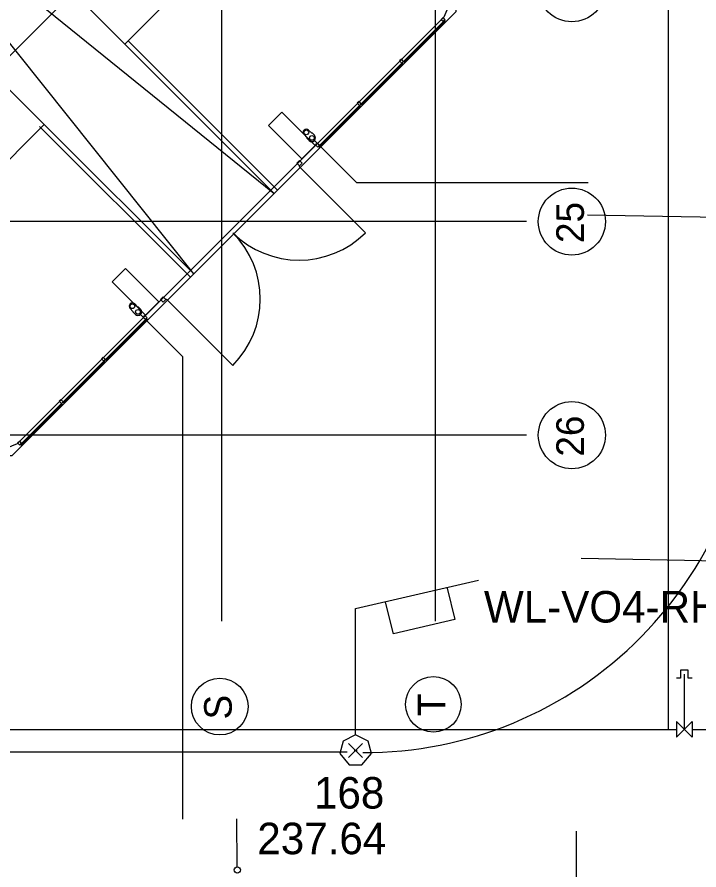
# Model space of a CAD drawing. Extents: x -264222 to -263592, y -1242345 to -1242048.
# Drawn here: x -263808.81 to -263787.18, y -1242254.6 to -1242227.54 of the extents above; entities that cross this region are included whole.
import ezdxf

# ---------------------------------------------------------------- set-up
doc = ezdxf.new("R2010")
doc.units = 0
for name, color, linetype in [('BOD_CISLO', 7, 'Continuous'), ('BOD_SYMBOL', 7, 'Continuous'), ('BOD_VYSKA', 7, 'Continuous'), ('HESCON_OSI_STAVBY_KFA', 7, 'Continuous'), ('KFA_2D_SITUACIA_DSP', 7, 'Continuous'), ('KFA_SO_62-1_VO_LAMPY_MERANE', 7, 'Continuous'), ('KFA_SO_62-1_VO_POPIS_LAMP_PROJEKT', 7, 'Continuous'), ('KFA_SO_62-1_VO_TRASA_KABLOV_PROJEKT', 7, 'Continuous')]:
    doc.layers.add(name, color=color, linetype=linetype)

msp = doc.modelspace()

# ---------------------------------------------------------------- linework, layer by layer
at = {"layer": 'BOD_SYMBOL'}
for p, q in [((-263798.289, -1242251.029), (-263797.847, -1242250.587)), ((-263797.847, -1242251.029), (-263798.289, -1242250.587))]:
    msp.add_line(p, q, dxfattribs=at)
at = {"layer": 'HESCON_OSI_STAVBY_KFA'}
for p, q in [((-263802.318, -1242083.237), (-263802.318, -1242246.707)), ((-263795.543, -1242083.237), (-263795.543, -1242246.707)), ((-263792.653, -1242234.032), (-263911.523, -1242234.032)), ((-263792.653, -1242234.032), (-263792.653, -1242234.032)), ((-263792.653, -1242240.807), (-263911.523, -1242240.807)), ((-263792.653, -1242240.807), (-263792.653, -1242240.807))]:
    msp.add_line(p, q, dxfattribs=at)
for centre, radius in [((-263791.21, -1242226.632), 1.064), ((-263791.21, -1242234.032), 1.064), ((-263791.21, -1242240.807), 1.064), ((-263802.378, -1242249.416), 0.899), ((-263795.603, -1242249.345), 0.882)]:
    msp.add_circle(centre, radius, dxfattribs=at)
at = {"layer": 'KFA_2D_SITUACIA_DSP'}
for p, q in [((-263788.143, -1242250.14), (-263788.143, -1242082.64)), ((-263795.043, -1242226.995), (-263795.272, -1242227.55)), ((-263795.272, -1242227.55), (-263808.8, -1242241.078)), ((-263796.558, -1242228.963), (-263795.25, -1242227.654)), ((-263795.232, -1242227.672), (-263796.541, -1242228.98)), ((-263795.297, -1242227.56), (-263795.354, -1242227.617)), ((-263795.354, -1242227.617), (-263795.283, -1242227.688)), ((-263795.227, -1242227.631), (-263795.297, -1242227.56)), ((-263795.283, -1242227.688), (-263795.255, -1242227.659)), ((-263795.255, -1242227.659), (-263795.227, -1242227.631)), ((-263795.25, -1242227.654), (-263795.232, -1242227.672)), ((-263805.283, -1242228.297), (-263800.546, -1242233.035)), ((-263805.389, -1242228.403), (-263800.652, -1242233.141)), ((-263796.59, -1242228.994), (-263797.898, -1242230.303)), ((-263797.881, -1242230.32), (-263796.572, -1242229.012)), ((-263796.617, -1242228.879), (-263796.673, -1242228.936)), ((-263796.673, -1242228.936), (-263796.602, -1242229.007)), ((-263796.546, -1242228.95), (-263796.617, -1242228.879)), ((-263796.602, -1242229.007), (-263796.574, -1242228.978)), ((-263796.572, -1242229.012), (-263796.59, -1242228.994)), ((-263796.574, -1242228.978), (-263796.546, -1242228.95)), ((-263796.541, -1242228.98), (-263796.558, -1242228.963)), ((-263797.961, -1242230.223), (-263798.017, -1242230.28)), ((-263797.89, -1242230.294), (-263797.961, -1242230.223)), ((-263797.934, -1242230.338), (-263799.242, -1242231.647)), ((-263799.225, -1242231.664), (-263797.916, -1242230.356)), ((-263798.017, -1242230.28), (-263797.946, -1242230.351)), ((-263797.946, -1242230.351), (-263797.918, -1242230.322)), ((-263797.916, -1242230.356), (-263797.934, -1242230.338)), ((-263797.918, -1242230.322), (-263797.89, -1242230.294)), ((-263797.898, -1242230.303), (-263797.881, -1242230.32)), ((-263800.834, -1242230.985), (-263800.41, -1242230.561)), ((-263800.41, -1242230.561), (-263799.349, -1242231.622)), ((-263808.093, -1242231.016), (-263803.31, -1242235.799)), ((-263807.987, -1242230.91), (-263803.204, -1242235.693)), ((-263799.774, -1242232.046), (-263800.834, -1242230.985)), ((-263799.705, -1242231.275), (-263799.617, -1242231.364)), ((-263799.559, -1242231.13), (-263799.471, -1242231.218)), ((-263799.471, -1242231.218), (-263799.451, -1242231.218)), ((-263799.373, -1242231.296), (-263799.451, -1242231.218)), ((-263799.451, -1242231.218), (-263799.373, -1242231.296)), ((-263799.617, -1242231.364), (-263799.617, -1242231.383)), ((-263799.617, -1242231.383), (-263799.538, -1242231.462)), ((-263799.402, -1242231.432), (-263798.041, -1242232.793)), ((-263799.28, -1242231.543), (-263799.336, -1242231.599)), ((-263799.209, -1242231.613), (-263799.28, -1242231.543)), ((-263799.349, -1242231.622), (-263799.774, -1242232.046)), ((-263799.336, -1242231.599), (-263799.266, -1242231.67)), ((-263799.266, -1242231.67), (-263799.237, -1242231.642)), ((-263799.242, -1242231.647), (-263799.225, -1242231.664)), ((-263799.237, -1242231.642), (-263799.209, -1242231.613)), ((-263799.929, -1242232.178), (-263799.844, -1242232.093)), ((-263799.844, -1242232.093), (-263799.759, -1242232.178)), ((-263799.844, -1242232.263), (-263799.929, -1242232.178)), ((-263799.844, -1242232.263), (-263799.862, -1242232.281)), ((-263799.862, -1242232.281), (-263797.758, -1242234.384)), ((-263799.759, -1242232.178), (-263799.844, -1242232.263)), ((-263798.041, -1242232.793), (-263790.695, -1242232.793)), ((-263781.818, -1242233.99), (-263790.714, -1242233.827)), ((-263805.365, -1242235.516), (-263805.789, -1242235.94)), ((-263804.304, -1242236.576), (-263805.365, -1242235.516)), ((-263805.789, -1242235.94), (-263804.728, -1242237.001)), ((-263804.172, -1242236.421), (-263804.257, -1242236.506)), ((-263804.087, -1242236.506), (-263804.172, -1242236.421)), ((-263805.075, -1242236.645), (-263804.986, -1242236.733)), ((-263804.728, -1242237.001), (-263804.304, -1242236.576)), ((-263804.257, -1242236.506), (-263804.172, -1242236.591)), ((-263804.172, -1242236.591), (-263804.087, -1242236.506)), ((-263804.087, -1242236.506), (-263804.069, -1242236.488)), ((-263804.069, -1242236.488), (-263801.966, -1242238.592)), ((-263805.22, -1242236.791), (-263805.132, -1242236.879)), ((-263805.132, -1242236.879), (-263805.132, -1242236.899)), ((-263805.132, -1242236.899), (-263805.054, -1242236.977)), ((-263804.986, -1242236.733), (-263804.967, -1242236.733)), ((-263804.888, -1242236.812), (-263804.967, -1242236.733)), ((-263804.967, -1242236.733), (-263804.888, -1242236.812)), ((-263804.918, -1242236.948), (-263803.556, -1242238.308)), ((-263806.012, -1242238.416), (-263804.703, -1242237.108)), ((-263804.686, -1242237.125), (-263805.994, -1242238.434)), ((-263804.807, -1242237.07), (-263804.751, -1242237.014)), ((-263804.737, -1242237.141), (-263804.807, -1242237.07)), ((-263804.751, -1242237.014), (-263804.68, -1242237.084)), ((-263804.708, -1242237.113), (-263804.737, -1242237.141)), ((-263804.68, -1242237.084), (-263804.708, -1242237.113)), ((-263804.703, -1242237.108), (-263804.686, -1242237.125)), ((-263806.127, -1242238.389), (-263806.07, -1242238.333)), ((-263806.07, -1242238.333), (-263805.999, -1242238.404)), ((-263803.556, -1242238.308), (-263803.556, -1242252.989)), ((-263807.356, -1242239.76), (-263806.047, -1242238.452)), ((-263806.03, -1242238.469), (-263807.338, -1242239.778)), ((-263806.056, -1242238.46), (-263806.127, -1242238.389)), ((-263806.028, -1242238.432), (-263806.056, -1242238.46)), ((-263806.047, -1242238.452), (-263806.03, -1242238.469)), ((-263805.999, -1242238.404), (-263806.028, -1242238.432)), ((-263805.994, -1242238.434), (-263806.012, -1242238.416)), ((-263807.471, -1242239.733), (-263807.414, -1242239.677)), ((-263807.414, -1242239.677), (-263807.343, -1242239.748)), ((-263807.387, -1242239.792), (-263808.696, -1242241.1)), ((-263808.678, -1242241.118), (-263807.37, -1242239.809)), ((-263807.4, -1242239.804), (-263807.471, -1242239.733)), ((-263807.372, -1242239.776), (-263807.4, -1242239.804)), ((-263807.37, -1242239.809), (-263807.387, -1242239.792)), ((-263807.343, -1242239.748), (-263807.372, -1242239.776)), ((-263807.338, -1242239.778), (-263807.356, -1242239.76)), ((-263808.79, -1242241.053), (-263808.733, -1242240.996)), ((-263808.733, -1242240.996), (-263808.662, -1242241.067)), ((-263808.8, -1242241.078), (-263809.355, -1242241.307)), ((-263808.719, -1242241.123), (-263808.79, -1242241.053)), ((-263808.691, -1242241.095), (-263808.719, -1242241.123)), ((-263808.696, -1242241.1), (-263808.678, -1242241.118)), ((-263808.662, -1242241.067), (-263808.691, -1242241.095)), ((-263781.818, -1242244.885), (-263790.914, -1242244.718)), ((-263787.768, -1242248.265), (-263787.768, -1242248.515)), ((-263787.518, -1242248.265), (-263787.768, -1242248.265)), ((-263787.518, -1242248.515), (-263787.518, -1242248.265)), ((-263787.768, -1242248.515), (-263787.893, -1242248.515)), ((-263787.643, -1242250.14), (-263787.643, -1242248.39)), ((-263787.393, -1242248.515), (-263787.518, -1242248.515)), ((-263787.893, -1242250.39), (-263787.393, -1242249.89)), ((-263787.893, -1242249.89), (-263787.893, -1242250.39)), ((-263787.393, -1242250.39), (-263787.893, -1242249.89)), ((-263787.393, -1242249.89), (-263787.393, -1242250.39)), ((-263924.143, -1242250.14), (-263788.143, -1242250.14)), ((-263788.143, -1242250.14), (-263787.893, -1242250.14)), ((-263788.143, -1242250.14), (-263787.893, -1242250.14)), ((-263787.393, -1242250.14), (-263786.693, -1242250.14)), ((-263801.822, -1242254.497), (-263801.837, -1242252.972)), ((-263791.063, -1242265.427), (-263791.063, -1242253.362))]:
    msp.add_line(p, q, dxfattribs=at)
for points in [[(-263794.893, -1242227.382), (-263808.968, -1242241.457), (-263894.968, -1242241.457), (-263909.043, -1242227.382), (-263909.043, -1242196.333), (-263914.143, -1242196.333), (-263914.143, -1242132.433), (-263909.043, -1242132.433), (-263909.043, -1242101.382), (-263894.968, -1242087.307), (-263808.968, -1242087.307), (-263794.893, -1242101.382), (-263794.893, -1242227.382)], [(-263909.043, -1242125.432), (-263902.343, -1242125.432), (-263902.343, -1242104.482), (-263902.112, -1242103.927), (-263898.54, -1242100.355), (-263895.995, -1242097.81), (-263892.423, -1242094.238), (-263891.868, -1242094.007), (-263812.071, -1242094.007), (-263811.513, -1242094.238), (-263801.823, -1242103.927), (-263801.593, -1242104.482), (-263801.593, -1242224.282), (-263801.824, -1242224.838), (-263805.392, -1242228.407)], [(-263811.918, -1242108.434), (-263811.918, -1242220.33), (-263812.262, -1242220.675), (-263809.862, -1242221.669), (-263810.999, -1242222.806), (-263807.039, -1242226.765), (-263809.585, -1242229.311), (-263813.545, -1242225.351), (-263814.681, -1242226.488), (-263815.675, -1242224.088), (-263816.02, -1242224.432), (-263887.916, -1242224.432), (-263888.26, -1242224.088), (-263889.254, -1242226.488), (-263890.391, -1242225.351), (-263894.351, -1242229.311), (-263896.896, -1242226.765), (-263892.937, -1242222.806), (-263894.073, -1242221.669), (-263891.673, -1242220.675), (-263892.018, -1242220.33), (-263892.018, -1242181.432)], [(-263807.941, -1242230.956), (-263813.544, -1242225.352), (-263814.681, -1242226.488), (-263815.675, -1242224.088), (-263812.262, -1242220.675)], [(-263812.262, -1242220.675), (-263809.863, -1242221.669), (-263810.999, -1242222.806), (-263805.392, -1242228.407)], [(-263803.204, -1242235.693), (-263813.559, -1242222.704), (-263800.652, -1242233.141)], [(-263807.942, -1242230.956), (-263811.512, -1242234.526), (-263812.068, -1242234.757), (-263891.868, -1242234.757), (-263892.424, -1242234.526), (-263895.994, -1242230.956)]]:
    msp.add_lwpolyline(points, dxfattribs=at)
for centre, radius in [((-263799.632, -1242231.202), 0.075), ((-263799.455, -1242231.379), 0.075), ((-263805.148, -1242236.718), 0.075), ((-263804.971, -1242236.895), 0.075), ((-263801.821, -1242254.597), 0.1)]:
    msp.add_circle(centre, radius, dxfattribs=at)
for centre, radius, start, end in [((-263799.632, -1242231.202), 0.103, 45, 225), ((-263799.455, -1242231.379), 0.117, 225, 45), ((-263804.069, -1242236.488), 2.975, 315.0001, 45.0001), ((-263799.862, -1242232.281), 2.975, 224.9999, 314.9999), ((-263805.148, -1242236.718), 0.103, 45, 225), ((-263804.971, -1242236.895), 0.117, 225, 45)]:
    msp.add_arc(centre, radius, start, end, dxfattribs=at)
at = {"layer": 'KFA_SO_62-1_VO_LAMPY_MERANE'}
for p, q in [((-263798.118, -1242250.808), (-263798.018, -1242250.808)), ((-263798.068, -1242250.808), (-263798.068, -1242250.808))]:
    msp.add_line(p, q, dxfattribs=at)
for points in [[(-263798.068, -1242250.308), (-263798.468, -1242250.508), (-263798.568, -1242250.908), (-263798.268, -1242251.258), (-263797.868, -1242251.258), (-263797.568, -1242250.908), (-263797.668, -1242250.508), (-263798.068, -1242250.308), (-263798.068, -1242246.308), (-263794.168, -1242245.408)], [(-263795.168, -1242245.658), (-263794.918, -1242246.658), (-263796.868, -1242247.108), (-263797.118, -1242246.108)]]:
    msp.add_lwpolyline(points, dxfattribs=at)
at = {"layer": 'KFA_SO_62-1_VO_TRASA_KABLOV_PROJEKT'}
msp.add_line((-263798.338, -1242250.863), (-263817.338, -1242250.863), dxfattribs=at)
msp.add_arc((-263797.796, -1242238.53), 12.345, 269.8043, 0.9179, dxfattribs=at)

# ---------------------------------------------------------------- texts
at = {"layer": 'BOD_CISLO'}
msp.add_text('168', height=1, dxfattribs=at).set_placement((-263799.389, -1242252.65))
at = {"layer": 'BOD_VYSKA'}
msp.add_text('237.64', height=1, dxfattribs=at).set_placement((-263801.186, -1242254.098))
at = {"layer": 'HESCON_OSI_STAVBY_KFA'}
for s, p in [('25', (-263790.829, -1242234.712)), ('26', (-263790.829, -1242241.487)), ('S', (-263801.997, -1242249.824)), ('T', (-263795.222, -1242249.718))]:
    msp.add_text(s, height=0.875, rotation=90, dxfattribs=at).set_placement(p)
at = {"layer": 'KFA_SO_62-1_VO_POPIS_LAMP_PROJEKT'}
msp.add_text('WL-VO4-RH2', height=1, dxfattribs=at).set_placement((-263793.999, -1242246.75))

doc.saveas('drawing.dxf')
